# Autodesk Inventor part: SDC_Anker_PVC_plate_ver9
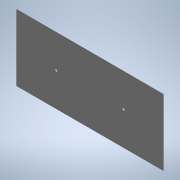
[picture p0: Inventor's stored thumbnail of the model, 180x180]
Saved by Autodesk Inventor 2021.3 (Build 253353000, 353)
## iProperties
Created: 2022-01
Part Number: SDC_Anker_PVC_plate_ver9
Material: PVC、無可塑
Document SubType Name: Modeling
Designer: kengo
Density: 1.29 g/cm^3
Appearance: 滑らか - 白
Author: kengo
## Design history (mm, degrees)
sketch "スケッチ1"
  geometry: L1 (-589.671, 316.432)-(590.329, 316.432); L2 (590.329, 316.432)-(590.329, -283.568); L3 (590.329, -283.568)-(-589.671, -283.568); L4 (-589.671, -283.568)-(-589.671, 316.432); 1 further point
  constraints: 8 end point, 2 parallel, 1 horizontal, 1 perpendicular
  dimensions: "d0" = 600 distance of L3.end L1.start; "d1" = 1180 distance of L1.start L1.end
extrude "押し出し1" new body sketch "スケッチ1" distance "d2" = 5; taper "d3" = 0 deg
sketch "スケッチ4"
  geometry: L1 (-589.671, 316.432)-(-589.671, -283.568) reference; L2 (590.329, -283.568)-(590.329, 316.432) reference; L3 (-589.671, 261.432)-(590.329, 261.432); L4 (590.329, 261.432)-(590.329, -228.568); L5 (590.329, -228.568)-(-589.671, -228.568); L6 (-589.671, -228.568)-(-589.671, 261.432); L7 (590.329, 316.432)-(-589.671, 316.432) reference; L8 (-589.671, -283.568)-(590.329, -283.568) reference; L9 (-589.671, 316.432)-(590.329, 316.432); L10 (590.329, 316.432)-(590.329, -283.568); L11 (590.329, -283.568)-(-589.671, -283.568); L12 (-589.671, -283.568)-(-589.671, 316.432); 3 further points
  constraints: 16 end point, 4 parallel, 2 horizontal, 2 perpendicular, 2 point on line
  dimensions: "d58" = 490 distance between parallel lines of L5 L3; "d59" = 55 distance between parallel lines of L7 L3
extrude "押し出し2" cut sketch "スケッチ4" distance "d60" = 30; taper "d61" = 0 deg
sketch "スケッチ8"
  geometry: L1 (-589.671, 261.432)-(590.329, 261.432) reference; L2 (590.329, -228.568)-(-589.671, -228.568) reference; L3 (-499.671, 261.432)-(-589.671, 261.432); L4 (-589.671, 261.432)-(-589.671, -228.568); L5 (-589.671, -228.568)-(-499.671, -228.568); L6 (-499.671, -228.568)-(-499.671, 261.432); 3 further points
  constraints: 8 end point, 2 parallel, 1 horizontal, 1 perpendicular, 1 point on line
  dimensions: "d119" = 90 distance between parallel lines of L4 L6
extrude "押し出し4" cut sketch "スケッチ8" distance "d120" = 20; taper "d121" = 0 deg
sketch "スケッチ10"
  geometry: L1 (-499.671, -228.568)-(590.329, -228.568) reference; C1 r 3.324 at (-204.671, 131.432) reference; C2 r 3.324 at (295.329, 131.432) reference; 3 further points
  dimensions: "d131" = 0 horizontal distance of C1.centre point (-204.671, 16.432); "d132" = 245 distance from line of L1 point (-204.671, 16.432); "d133" = 245 distance from line of L1 point (295.329, 16.432); "d134" = 0 horizontal distance of C2.centre point (295.329, 16.432)
hole "穴6" sketch "スケッチ10" at (-204.671, 16.432), (295.329, 16.432) diameter "d135" = 18; stored, may be unused: countersink angle "d139" = 90 deg, drill point angle "d141" = 118 deg; dims "d136" = 6, "d137" = 4, "d138" = 2, "d140" = 22.2
node "ソリッド1"
